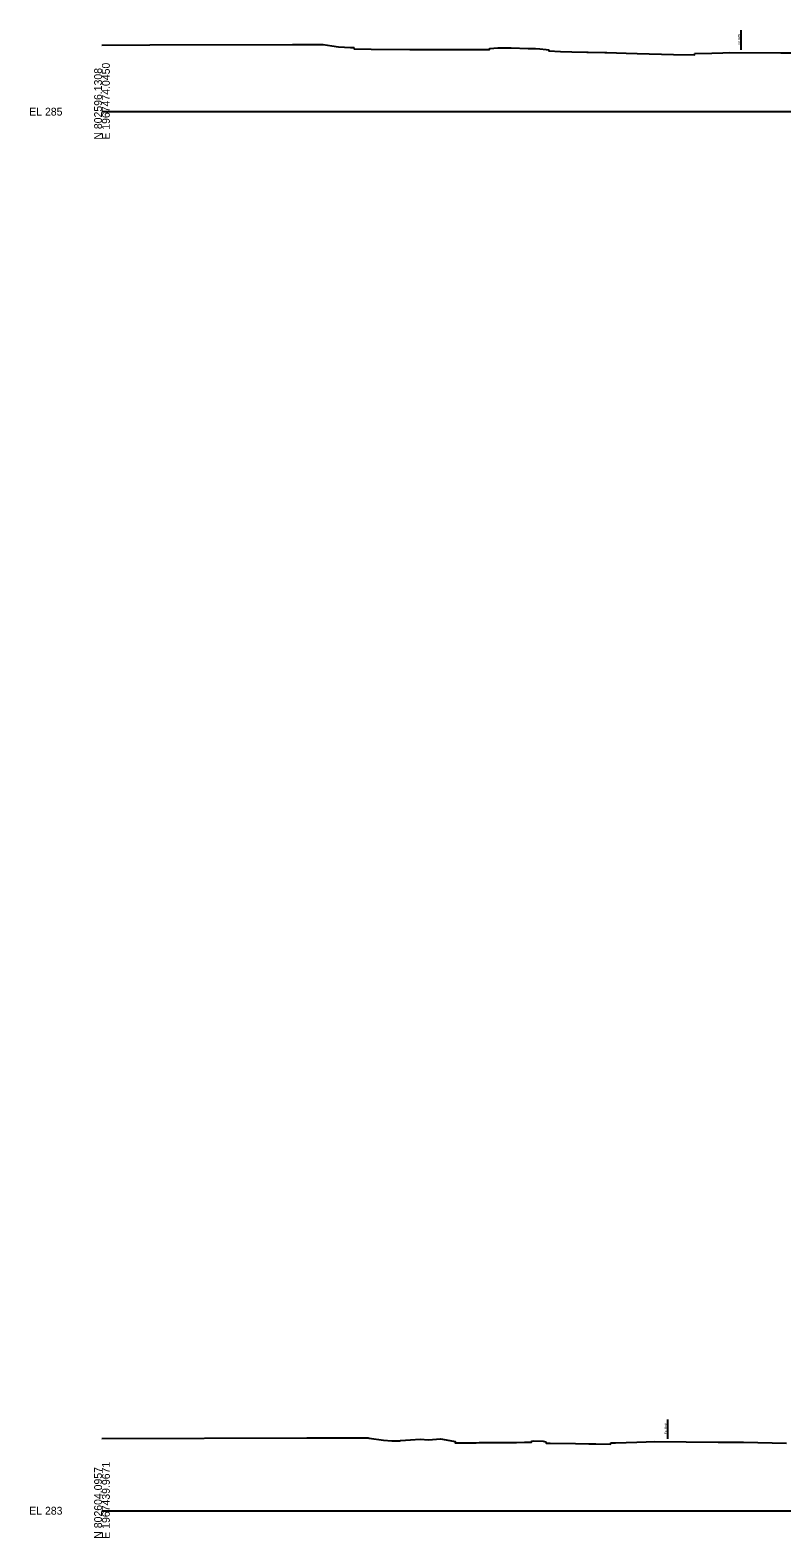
# Model space of a CAD drawing. Extents: x -26 to 1986619, y -10 to 827846.
# Drawn here: x -26 to 243, y 25490 to 26029 of the extents above; entities that cross this region are included whole.
import ezdxf

# ---------------------------------------------------------------- set-up
doc = ezdxf.new("R2010")
doc.units = 0
for name, color, linetype in [('Default', 7, 'Continuous'), ('RD_GPK_XS_Cell', 7, 'Continuous'), ('RD_XS_ExGround', 7, 'Continuous'), ('RD_XS_ExRW', 7, 'Continuous')]:
    doc.layers.add(name, color=color, linetype=linetype)

msp = doc.modelspace()

# ---------------------------------------------------------------- linework, layer by layer
at = {"layer": 'RD_GPK_XS_Cell'}
for p, q in [((0, 26000), (300, 26000)), ((0, 25500), (300, 25500))]:
    msp.add_line(p, q, dxfattribs=at)
at = {"layer": 'RD_XS_ExGround'}
for points in [[(0, 26023.74), (17.16, 26023.86), (68.12, 26024.02), (79.12, 26024), (82.24, 26023.5), (84.53, 26023.14), (88.91, 26022.97), (90.05, 26022.91), (90.16, 26022.46), (96.22, 26022.36), (110.07, 26022.18), (115.83, 26022.19), (136.96, 26022.17), (138.19, 26022.17), (138.58, 26022.16), (138.72, 26022.61), (141.6, 26022.75), (143.23, 26022.8), (144.12, 26022.81), (144.45, 26022.81), (145.16, 26022.84), (145.76, 26022.85), (146.37, 26022.84), (152.46, 26022.59), (153.8, 26022.56), (155.09, 26022.54), (156.6, 26022.46), (158.85, 26022.23), (159.72, 26022.14), (159.85, 26021.68), (163.97, 26021.5), (168.08, 26021.36), (173.38, 26021.28), (173.9, 26021.27), (179.88, 26021.13), (180.57, 26021.12), (187.51, 26020.95), (191.43, 26020.79), (204.42, 26020.44), (211.93, 26020.36), (212.04, 26020.81), (218.13, 26020.96), (222.05, 26021.05), (224.42, 26021.14), (242.8, 26021.07), (251.12, 26021.03)], [(0, 25525.83), (73.23, 25526.08), (95.14, 25526.04), (95.58, 25525.97), (100.73, 25525.18), (103.66, 25525.03), (106.16, 25524.93), (106.65, 25524.97), (106.77, 25525.12), (110.3, 25525.31), (113.75, 25525.56), (116.81, 25525.35), (121.02, 25525.72), (123.1, 25525.37), (126.26, 25524.77), (126.36, 25524.32), (130.62, 25524.31), (133.81, 25524.31), (134.87, 25524.35), (138.65, 25524.37), (144.71, 25524.38), (145.92, 25524.4), (148.22, 25524.43), (151.12, 25524.45), (153.59, 25524.45), (153.71, 25524.9), (154.44, 25524.97), (157.8, 25524.8), (158.76, 25524.63), (158.88, 25524.18), (159.24, 25524.17), (160.31, 25524.15), (169.28, 25524.01), (174.15, 25523.92), (176.66, 25523.87), (181.81, 25523.8), (181.97, 25524.24), (182.49, 25524.28), (183.69, 25524.29), (191.22, 25524.53), (194.65, 25524.62), (197.51, 25524.7), (220.3, 25524.48), (229.36, 25524.48), (244.8, 25524.16)]]:
    msp.add_lwpolyline(points, dxfattribs=at)
at = {"layer": 'RD_XS_ExRW'}
for p, q in [((228.53, 26022.13), (228.53, 26029.13)), ((202.3, 25525.66), (202.3, 25532.66))]:
    msp.add_line(p, q, dxfattribs=at)

# ---------------------------------------------------------------- texts
at = {"layer": 'Default'}
for p in [(0, 26000), (0, 25500)]:
    msp.add_text('-', height=0.0001, dxfattribs=at).set_placement(p)
at = {"layer": 'RD_GPK_XS_Cell'}
for s, p in [('N 802596.1308', (0, 25990)), ('E 1967474.0450', (2.8, 25990)), ('N 802604.0957', (0, 25490)), ('E 1967439.9671', (2.8, 25490))]:
    msp.add_text(s, height=2.8, rotation=90, dxfattribs=at).set_placement(p)
for s, p in [('EL 285', (-26, 25998.6)), ('EL 283', (-26, 25498.6))]:
    msp.add_text(s, height=2.8, dxfattribs=at).set_placement(p)
at = {"layer": 'RD_XS_ExRW'}
for p in [(228.23, 26023.81), (202.02, 25527.34)]:
    msp.add_text('EX. R/W ', height=0.75, rotation=90, dxfattribs=at).set_placement(p)

doc.saveas('drawing.dxf')
